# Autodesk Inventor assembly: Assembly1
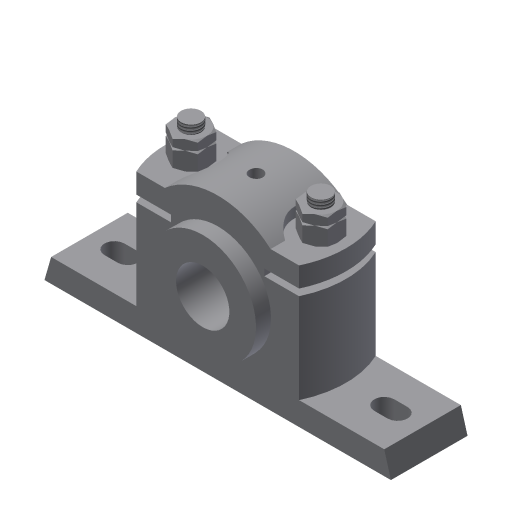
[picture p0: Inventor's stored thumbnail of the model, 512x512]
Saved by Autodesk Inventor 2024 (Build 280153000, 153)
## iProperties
Created: 2015-03
Part Number: Assembly1
Document SubType Name: Assembly
Designer: Sandeep
Author: Sandeep
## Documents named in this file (7)
- D:\PROJECTS\Project 2023\RESOURCES INVENTOR 2024\RESOURCES INVENTOR 2024\Inventor_2024_tut\Inventor_2024_tut\c11_Inv_2024_tut\c11_Inv_tut_2024\c11_tut02_inv\Plummer Block.iam
- D:\PROJECTS\Project 2023\RESOURCES INVENTOR 2024\RESOURCES INVENTOR 2024\Inventor_2024_tut\Inventor_2024_tut\c11_Inv_2024_tut\c11_Inv_tut_2024\c11_tut02_inv\Casting.ipt
- D:\PROJECTS\Project 2023\RESOURCES INVENTOR 2024\RESOURCES INVENTOR 2024\Inventor_2024_tut\Inventor_2024_tut\c11_Inv_2024_tut\c11_Inv_tut_2024\c11_tut02_inv\Brasses.ipt
- D:\PROJECTS\Project 2023\RESOURCES INVENTOR 2024\RESOURCES INVENTOR 2024\Inventor_2024_tut\Inventor_2024_tut\c11_Inv_2024_tut\c11_Inv_tut_2024\c11_tut02_inv\Cap.ipt
- D:\PROJECTS\Project 2023\RESOURCES INVENTOR 2024\RESOURCES INVENTOR 2024\Inventor_2024_tut\Inventor_2024_tut\c11_Inv_2024_tut\c11_Inv_tut_2024\c11_tut02_inv\Bolt.ipt
- D:\PROJECTS\Project 2023\RESOURCES INVENTOR 2024\RESOURCES INVENTOR 2024\Inventor_2024_tut\Inventor_2024_tut\c11_Inv_2024_tut\c11_Inv_tut_2024\c11_tut02_inv\Nut.ipt
- D:\PROJECTS\Project 2023\RESOURCES INVENTOR 2024\RESOURCES INVENTOR 2024\Inventor_2024_tut\Inventor_2024_tut\c11_Inv_2024_tut\c11_Inv_tut_2024\c11_tut02_inv\locknut.ipt
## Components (9 placed, 6 different names)
1. Casting:1 — Mate:1, Mate:2, Insert:1, Insert:2, Angle:1, Angle:2
2. Brasses:1 — Mate:1, Mate:2, Mate:3, Mate:4
3. Cap:1 — Mate:3, Mate:4, Insert:3, Insert:4
4. Bolt:1 — Insert:1, Angle:2
5. Bolt:2 — Insert:2, Angle:1
6. Nut:1 — Insert:3, Insert:5
7. Nut:2 — Insert:4, Insert:6
8. locknut:1 — Insert:5
9. locknut:2 — Insert:6
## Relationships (12: Insert 6, Mate 4, Angle 2)
- Mate:1: Casting:1 ↔ Brasses:1
- Mate:2: Casting:1 ↔ Brasses:1
- Mate:3: Brasses:1 ↔ Cap:1
- Mate:4: Brasses:1 ↔ Cap:1
- Insert:1: Casting:1 ↔ Bolt:1
- Insert:2: Casting:1 ↔ Bolt:2
- Angle:1: Casting:1 ↔ Bolt:2
- Angle:2: Casting:1 ↔ Bolt:1
- Insert:3: Cap:1 ↔ Nut:1
- Insert:4: Cap:1 ↔ Nut:2
- Insert:5: Nut:1 ↔ locknut:1
- Insert:6: Nut:2 ↔ locknut:2
